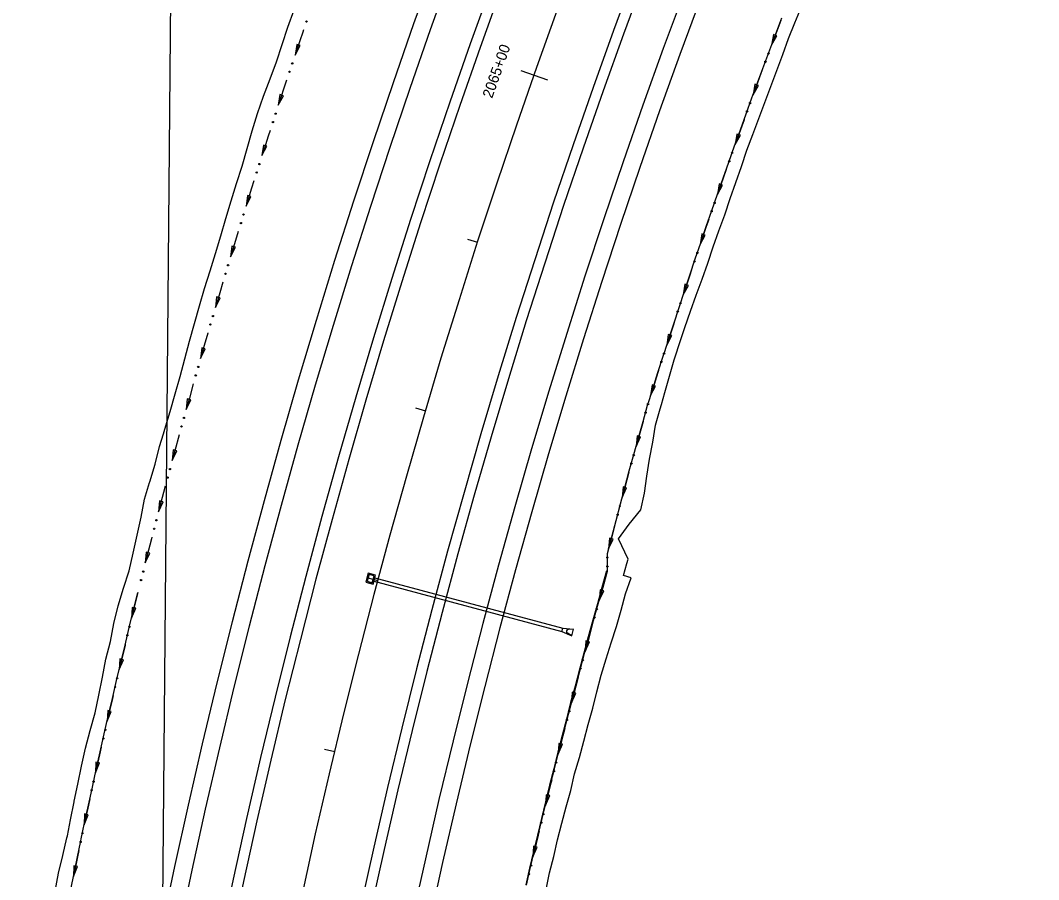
# Model space of a CAD drawing. Extents: x 1611108 to 1749517, y 619561 to 797725.
# Drawn here: x 1713533 to 1714111, y 763041 to 763528 of the extents above; entities that cross this region are included whole.
import ezdxf

# ---------------------------------------------------------------- set-up
doc = ezdxf.new("R2010")
doc.units = 0
for name, color, linetype in [('R_Ditch', 7, 'Continuous'), ('R_Drainage', 7, 'Continuous'), ('R_Horz Alg', 7, 'Continuous'), ('R_Horz Alg Annot', 7, 'Continuous'), ('R_Horz Alg Stationing', 7, 'Continuous'), ('R_Proposed Const Limits', 7, 'Continuous'), ('R_Proposed Road', 7, 'Continuous')]:
    doc.layers.add(name, color=color, linetype=linetype)

msp = doc.modelspace()

# ---------------------------------------------------------------- linework, layer by layer
at = {"layer": 'R_Ditch'}
for p, q in [((1713960.35, 763520.09), (1713959.23, 763514.1)), ((1713959.23, 763514.1), (1713962.33, 763519.35)), ((1713962.33, 763519.35), (1713960.35, 763520.09)), ((1713689.82, 763514.52), (1713688.9, 763508.5)), ((1713689.82, 763514.52), (1713688.9, 763508.5)), ((1713688.9, 763508.5), (1713691.82, 763513.85)), ((1713688.9, 763508.5), (1713691.82, 763513.85)), ((1713691.82, 763513.85), (1713689.82, 763514.52)), ((1713691.82, 763513.85), (1713689.82, 763514.52)), ((1713949.86, 763491.94), (1713948.79, 763485.94)), ((1713948.79, 763485.94), (1713951.85, 763491.21)), ((1713951.85, 763491.21), (1713949.86, 763491.94)), ((1713680.28, 763486.04), (1713679.39, 763480.01)), ((1713680.28, 763486.04), (1713679.39, 763480.01)), ((1713679.39, 763480.01), (1713682.29, 763485.37)), ((1713679.39, 763480.01), (1713682.29, 763485.37)), ((1713682.29, 763485.37), (1713680.28, 763486.04)), ((1713682.29, 763485.37), (1713680.28, 763486.04)), ((1713939.59, 763463.7), (1713938.56, 763457.7)), ((1713938.56, 763457.7), (1713941.58, 763462.99)), ((1713941.58, 763462.99), (1713939.59, 763463.7)), ((1713670.96, 763457.47), (1713670.13, 763451.43)), ((1713670.96, 763457.47), (1713670.13, 763451.43)), ((1713670.13, 763451.43), (1713672.97, 763456.82)), ((1713670.13, 763451.43), (1713672.97, 763456.82)), ((1713672.97, 763456.82), (1713670.96, 763457.47)), ((1713672.97, 763456.82), (1713670.96, 763457.47)), ((1713929.53, 763435.39), (1713928.54, 763429.38)), ((1713928.54, 763429.38), (1713931.52, 763434.69)), ((1713931.52, 763434.69), (1713929.53, 763435.39)), ((1713661.87, 763428.83), (1713661.09, 763422.79)), ((1713661.87, 763428.83), (1713661.09, 763422.79)), ((1713661.09, 763422.79), (1713663.89, 763428.2)), ((1713661.09, 763422.79), (1713663.89, 763428.2)), ((1713663.89, 763428.2), (1713661.87, 763428.83)), ((1713663.89, 763428.2), (1713661.87, 763428.83)), ((1713919.68, 763407.01), (1713918.74, 763400.99)), ((1713918.74, 763400.99), (1713921.68, 763406.32)), ((1713921.68, 763406.32), (1713919.68, 763407.01)), ((1713653, 763400.12), (1713652.27, 763394.08)), ((1713653, 763400.12), (1713652.27, 763394.08)), ((1713652.27, 763394.08), (1713655.03, 763399.51)), ((1713652.27, 763394.08), (1713655.03, 763399.51)), ((1713655.03, 763399.51), (1713653, 763400.12)), ((1713655.03, 763399.51), (1713653, 763400.12)), ((1713910.05, 763378.55), (1713909.15, 763372.52)), ((1713909.15, 763372.52), (1713912.05, 763377.88)), ((1713912.05, 763377.88), (1713910.05, 763378.55)), ((1713644.35, 763371.35), (1713643.66, 763365.3)), ((1713644.35, 763371.35), (1713643.66, 763365.3)), ((1713643.66, 763365.3), (1713646.38, 763370.75)), ((1713643.66, 763365.3), (1713646.38, 763370.75)), ((1713646.38, 763370.75), (1713644.35, 763371.35)), ((1713646.38, 763370.75), (1713644.35, 763371.35)), ((1713900.62, 763350.01), (1713899.78, 763343.98)), ((1713899.78, 763343.98), (1713902.64, 763349.36)), ((1713902.64, 763349.36), (1713900.62, 763350.01)), ((1713635.92, 763342.51), (1713635.28, 763336.45)), ((1713635.92, 763342.51), (1713635.28, 763336.45)), ((1713635.28, 763336.45), (1713637.95, 763341.93)), ((1713635.28, 763336.45), (1713637.95, 763341.93)), ((1713637.95, 763341.93), (1713635.92, 763342.51)), ((1713637.95, 763341.93), (1713635.92, 763342.51)), ((1713891.44, 763321.41), (1713890.64, 763315.37)), ((1713893.46, 763320.77), (1713891.44, 763321.41)), ((1713890.64, 763315.37), (1713893.46, 763320.77)), ((1713627.71, 763313.61), (1713627.11, 763307.55)), ((1713627.71, 763313.61), (1713627.11, 763307.55)), ((1713627.11, 763307.55), (1713629.74, 763313.04)), ((1713627.11, 763307.55), (1713629.74, 763313.04)), ((1713629.74, 763313.04), (1713627.71, 763313.61)), ((1713629.74, 763313.04), (1713627.71, 763313.61)), ((1713882.94, 763292.56), (1713882.36, 763286.5)), ((1713884.98, 763291.99), (1713882.94, 763292.56)), ((1713882.36, 763286.5), (1713884.98, 763291.99)), ((1713619.71, 763284.65), (1713619.17, 763278.58)), ((1713619.71, 763284.65), (1713619.17, 763278.58)), ((1713619.17, 763278.58), (1713621.76, 763284.09)), ((1713619.17, 763278.58), (1713621.76, 763284.09)), ((1713621.76, 763284.09), (1713619.71, 763284.65)), ((1713621.76, 763284.09), (1713619.71, 763284.65)), ((1713874.98, 763263.59), (1713874.45, 763257.52)), ((1713877.03, 763263.04), (1713874.98, 763263.59)), ((1713874.45, 763257.52), (1713877.03, 763263.04)), ((1713611.94, 763255.62), (1713611.44, 763249.55)), ((1713611.94, 763255.62), (1713611.44, 763249.55)), ((1713611.44, 763249.55), (1713613.99, 763255.09)), ((1713611.44, 763249.55), (1713613.99, 763255.09)), ((1713613.99, 763255.09), (1713611.94, 763255.62)), ((1713613.99, 763255.09), (1713611.94, 763255.62)), ((1713867.26, 763234.55), (1713866.77, 763228.48)), ((1713866.77, 763228.48), (1713869.31, 763234.02)), ((1713869.31, 763234.02), (1713867.26, 763234.55)), ((1713604.39, 763226.54), (1713603.94, 763220.46)), ((1713604.39, 763226.54), (1713603.94, 763220.46)), ((1713603.94, 763220.46), (1713606.44, 763226.02)), ((1713603.94, 763220.46), (1713606.44, 763226.02)), ((1713606.44, 763226.02), (1713604.39, 763226.54)), ((1713606.44, 763226.02), (1713604.39, 763226.54)), ((1713861.99, 763205.24), (1713861.39, 763199.18)), ((1713861.39, 763199.18), (1713864.03, 763204.67)), ((1713864.03, 763204.67), (1713861.99, 763205.24)), ((1713596.53, 763195.25), (1713596.13, 763189.17)), ((1713596.13, 763189.17), (1713598.59, 763194.75)), ((1713598.59, 763194.75), (1713596.53, 763195.25)), ((1713853.97, 763176.28), (1713853.42, 763170.22)), ((1713853.42, 763170.22), (1713856.01, 763175.73)), ((1713856.01, 763175.73), (1713853.97, 763176.28)), ((1713589.44, 763166.05), (1713589.09, 763159.97)), ((1713589.09, 763159.97), (1713591.5, 763165.57)), ((1713591.5, 763165.57), (1713589.44, 763166.05)), ((1713846.19, 763147.26), (1713845.68, 763141.19)), ((1713845.68, 763141.19), (1713848.23, 763146.72)), ((1713848.23, 763146.72), (1713846.19, 763147.26)), ((1713582.58, 763136.8), (1713582.26, 763130.72)), ((1713584.64, 763136.33), (1713582.58, 763136.8)), ((1713582.26, 763130.72), (1713584.64, 763136.33)), ((1713838.64, 763118.18), (1713838.18, 763112.1)), ((1713838.18, 763112.1), (1713840.69, 763117.66)), ((1713840.69, 763117.66), (1713838.64, 763118.18)), ((1713575.93, 763107.5), (1713575.66, 763101.42)), ((1713578, 763107.04), (1713575.93, 763107.5)), ((1713575.66, 763101.42), (1713578, 763107.04)), ((1713831.32, 763089.04), (1713830.91, 763082.96)), ((1713830.91, 763082.96), (1713833.38, 763088.53)), ((1713833.38, 763088.53), (1713831.32, 763089.04)), ((1713569.51, 763078.15), (1713569.28, 763072.06)), ((1713569.28, 763072.06), (1713571.58, 763077.71)), ((1713571.58, 763077.71), (1713569.51, 763078.15)), ((1713824.24, 763059.83), (1713823.89, 763053.75)), ((1713823.89, 763053.75), (1713826.3, 763059.35)), ((1713826.3, 763059.35), (1713824.24, 763059.83)), ((1713563.31, 763048.75), (1713563.13, 763042.66)), ((1713563.13, 763042.66), (1713565.38, 763048.32)), ((1713565.38, 763048.32), (1713563.31, 763048.75))]:
    msp.add_line(p, q, dxfattribs=at)
for points in [[(1713820.17, 763037.83), (1713822.36, 763047.26), (1713824.58, 763056.68), (1713826.83, 763066.09), (1713829.1, 763075.5), (1713831.39, 763084.9), (1713833.71, 763094.3), (1713836.05, 763103.68), (1713838.42, 763113.07), (1713840.82, 763122.44), (1713843.23, 763131.81), (1713845.68, 763141.18), (1713848.14, 763150.53), (1713850.63, 763159.88), (1713853.15, 763169.23), (1713855.69, 763178.56), (1713858.25, 763187.89), (1713860.84, 763197.21), (1713863.45, 763206.53), (1713866.09, 763215.84), (1713866.09, 763225.89), (1713868.54, 763235.26), (1713871, 763244.62), (1713873.5, 763253.98), (1713876.01, 763263.33), (1713878.55, 763272.68), (1713881.12, 763282.02), (1713883.71, 763291.36), (1713886.32, 763300.69), (1713888.96, 763310.01), (1713889.75, 763312.51), (1713891.87, 763319.25), (1713894.8, 763328.48), (1713897.75, 763337.7), (1713898.45, 763339.88), (1713900.73, 763346.92), (1713903.74, 763356.13), (1713906.77, 763365.33), (1713909.81, 763374.52), (1713912.89, 763383.71), (1713915.98, 763392.89), (1713919.1, 763402.06), (1713922.24, 763411.22), (1713925.4, 763420.37), (1713928.59, 763429.52), (1713931.79, 763438.66), (1713935.02, 763447.79), (1713938.27, 763456.91), (1713941.55, 763466.02), (1713944.84, 763475.13), (1713948.16, 763484.23), (1713951.5, 763493.32), (1713954.86, 763502.4), (1713958.24, 763511.47), (1713961.65, 763520.54), (1713965.07, 763529.59)], [(1713964.52, 763528.14), (1713961.65, 763520.54), (1713959.23, 763514.1)], [(1713693.73, 763522.7), (1713693.29, 763521.41), (1713689.95, 763511.61), (1713688.9, 763508.5)], [(1713693.73, 763522.7), (1713693.29, 763521.41), (1713689.95, 763511.61), (1713688.9, 763508.5)], [(1713693.74, 763522.74), (1713693.73, 763522.7)], [(1713693.74, 763522.74), (1713693.73, 763522.7)], [(1713953.98, 763500.01), (1713951.5, 763493.32), (1713948.79, 763485.94)], [(1713953.99, 763500.05), (1713953.98, 763500.01)], [(1713684.12, 763494.24), (1713683.37, 763492), (1713680.11, 763482.18), (1713679.4, 763480.01)], [(1713684.12, 763494.24), (1713683.37, 763492), (1713680.11, 763482.18), (1713679.4, 763480.01)], [(1713684.13, 763494.28), (1713684.12, 763494.25)], [(1713684.13, 763494.28), (1713684.12, 763494.25)], [(1713943.64, 763471.81), (1713941.55, 763466.02), (1713938.56, 763457.7)], [(1713943.65, 763471.85), (1713943.64, 763471.81)], [(1713674.73, 763465.71), (1713673.69, 763462.51), (1713670.52, 763452.66), (1713670.13, 763451.43)], [(1713674.73, 763465.71), (1713673.69, 763462.51), (1713670.52, 763452.66), (1713670.13, 763451.43)], [(1713674.74, 763465.75), (1713674.73, 763465.71)], [(1713674.74, 763465.75), (1713674.73, 763465.71)], [(1713933.52, 763443.53), (1713931.79, 763438.66), (1713928.59, 763429.52), (1713928.54, 763429.38)], [(1713933.53, 763443.57), (1713933.52, 763443.53)], [(1713665.58, 763437.1), (1713664.27, 763432.94), (1713661.18, 763423.07), (1713661.09, 763422.79)], [(1713665.58, 763437.1), (1713664.27, 763432.94), (1713661.18, 763423.07), (1713661.09, 763422.79)], [(1713665.59, 763437.14), (1713665.58, 763437.1)], [(1713665.59, 763437.14), (1713665.58, 763437.1)], [(1713923.61, 763415.17), (1713922.24, 763411.22), (1713919.1, 763402.06), (1713918.74, 763400.99)], [(1713923.62, 763415.21), (1713923.61, 763415.17)], [(1713656.65, 763408.42), (1713655.08, 763403.31), (1713652.27, 763394.08)], [(1713656.65, 763408.42), (1713655.08, 763403.31), (1713652.27, 763394.08)], [(1713656.66, 763408.46), (1713656.65, 763408.42)], [(1713656.66, 763408.46), (1713656.65, 763408.42)], [(1713913.91, 763386.74), (1713912.89, 763383.71), (1713909.81, 763374.52), (1713909.15, 763372.52)], [(1713913.92, 763386.78), (1713913.91, 763386.74)], [(1713647.93, 763379.68), (1713646.12, 763373.6), (1713643.66, 763365.3)], [(1713647.93, 763379.68), (1713646.12, 763373.6), (1713643.66, 763365.3)], [(1713647.94, 763379.71), (1713647.93, 763379.68)], [(1713647.94, 763379.71), (1713647.93, 763379.68)], [(1713904.43, 763358.24), (1713903.74, 763356.13), (1713900.73, 763346.92), (1713899.78, 763343.98)], [(1713904.44, 763358.28), (1713904.43, 763358.24)], [(1713639.44, 763350.86), (1713637.39, 763343.82), (1713635.28, 763336.45)], [(1713639.44, 763350.86), (1713637.39, 763343.82), (1713635.28, 763336.45)], [(1713639.45, 763350.9), (1713639.44, 763350.86)], [(1713639.45, 763350.9), (1713639.44, 763350.86)], [(1713895.18, 763329.66), (1713894.8, 763328.48), (1713891.87, 763319.25), (1713890.64, 763315.37)], [(1713895.19, 763329.7), (1713895.18, 763329.66)], [(1713631.16, 763321.99), (1713628.91, 763313.97), (1713627.11, 763307.55)], [(1713631.16, 763321.99), (1713628.91, 763313.97), (1713627.11, 763307.55)], [(1713631.17, 763322.02), (1713631.16, 763321.99)], [(1713631.17, 763322.02), (1713631.16, 763321.99)], [(1713886.39, 763300.94), (1713886.32, 763300.69), (1713883.71, 763291.36), (1713882.36, 763286.5)], [(1713886.4, 763300.98), (1713886.39, 763300.94)], [(1713623.11, 763293.05), (1713620.65, 763284.06), (1713619.17, 763278.58)], [(1713623.11, 763293.05), (1713620.65, 763284.06), (1713619.17, 763278.58)], [(1713623.12, 763293.09), (1713623.11, 763293.05)], [(1713623.12, 763293.09), (1713623.11, 763293.05)], [(1713878.37, 763272), (1713876.01, 763263.33), (1713874.45, 763257.52)], [(1713878.38, 763272.03), (1713878.37, 763272)], [(1713615.27, 763264.05), (1713612.63, 763254.09), (1713611.44, 763249.55)], [(1713615.27, 763264.05), (1713612.63, 763254.09), (1713611.44, 763249.55)], [(1713615.28, 763264.09), (1713615.27, 763264.05)], [(1713615.28, 763264.09), (1713615.27, 763264.05)], [(1713870.57, 763242.99), (1713868.54, 763235.26), (1713866.77, 763228.48)], [(1713870.58, 763243.02), (1713870.57, 763242.99)], [(1713607.66, 763235), (1713607.42, 763234.08), (1713604.85, 763224.06), (1713603.94, 763220.46)], [(1713607.66, 763235), (1713607.42, 763234.08), (1713604.85, 763224.06), (1713603.94, 763220.46)], [(1713607.67, 763235.03), (1713607.66, 763235)], [(1713607.67, 763235.03), (1713607.66, 763235)], [(1713865.69, 763215.95), (1713863.05, 763206.64), (1713860.44, 763197.32), (1713857.85, 763188), (1713855.29, 763178.67), (1713852.75, 763169.33), (1713850.23, 763159.99), (1713847.74, 763150.64), (1713845.27, 763141.28), (1713842.83, 763131.91), (1713840.41, 763122.54), (1713838.02, 763113.17), (1713835.65, 763103.78), (1713833.31, 763094.39), (1713830.99, 763085), (1713828.7, 763075.59), (1713826.43, 763066.19), (1713824.18, 763056.77), (1713821.96, 763047.35), (1713819.76, 763037.92)], [(1713865.46, 763213.61), (1713863.45, 763206.53), (1713861.39, 763199.18)], [(1713865.47, 763213.65), (1713865.46, 763213.61)], [(1713561.08, 763032.57), (1713563.14, 763042.7), (1713565.23, 763052.83), (1713567.35, 763062.94), (1713567.6, 763064.1), (1713569.5, 763073.06), (1713571.67, 763083.17), (1713573.87, 763093.27), (1713576.09, 763103.37), (1713578.34, 763113.46), (1713580.62, 763123.54), (1713582.93, 763133.62), (1713585.26, 763143.69), (1713587.61, 763153.76), (1713590, 763163.82), (1713592.41, 763173.88), (1713594.84, 763183.93), (1713597.31, 763193.97), (1713599.73, 763203.73), (1713599.73, 763203.73)], [(1713599.73, 763203.73), (1713597.31, 763193.97), (1713596.13, 763189.17)], [(1713857.37, 763184.69), (1713855.69, 763178.56), (1713853.42, 763170.22)], [(1713857.38, 763184.72), (1713857.37, 763184.69)], [(1713592.57, 763174.56), (1713592.41, 763173.88), (1713590, 763163.82), (1713589.09, 763159.97)], [(1713592.58, 763174.6), (1713592.57, 763174.56)], [(1713849.52, 763155.69), (1713848.14, 763150.53), (1713845.68, 763141.19)], [(1713849.52, 763155.73), (1713849.52, 763155.69)], [(1713585.64, 763145.33), (1713585.26, 763143.69), (1713582.93, 763133.62), (1713582.26, 763130.72)], [(1713585.65, 763145.37), (1713585.64, 763145.33)], [(1713841.9, 763126.64), (1713840.82, 763122.44), (1713838.42, 763113.07), (1713838.18, 763112.1)], [(1713841.91, 763126.67), (1713841.9, 763126.64)], [(1713578.93, 763116.05), (1713578.34, 763113.46), (1713576.09, 763103.37), (1713575.66, 763101.41)], [(1713578.94, 763116.09), (1713578.93, 763116.05)], [(1713834.52, 763097.52), (1713833.71, 763094.3), (1713831.39, 763084.9), (1713830.92, 763082.96)], [(1713834.53, 763097.56), (1713834.52, 763097.52)], [(1713572.44, 763086.73), (1713571.67, 763083.17), (1713569.5, 763073.06), (1713569.29, 763072.06)], [(1713572.45, 763086.76), (1713572.44, 763086.73)], [(1713827.37, 763068.34), (1713826.83, 763066.09), (1713824.58, 763056.68), (1713823.89, 763053.75)], [(1713827.38, 763068.38), (1713827.37, 763068.34)], [(1713566.18, 763057.35), (1713565.23, 763052.83), (1713563.14, 763042.7), (1713563.13, 763042.66)], [(1713566.19, 763057.38), (1713566.18, 763057.35)]]:
    msp.add_lwpolyline(points, dxfattribs=at)
for centre in [(1713695.4, 763527.44), (1713695.4, 763527.44), (1713957.51, 763509.4), (1713687.34, 763503.75), (1713687.34, 763503.75), (1713955.76, 763504.71), (1713685.74, 763499), (1713685.74, 763499), (1713947.1, 763481.23), (1713677.87, 763475.24), (1713677.87, 763475.24), (1713945.39, 763476.52), (1713676.32, 763470.48), (1713676.32, 763470.48), (1713935.23, 763448.25), (1713936.91, 763452.97), (1713668.64, 763446.65), (1713668.64, 763446.65), (1713667.13, 763441.88), (1713667.13, 763441.88), (1713925.28, 763419.91), (1713926.93, 763424.64), (1713659.64, 763418), (1713659.64, 763418), (1713658.16, 763413.21), (1713658.16, 763413.21), (1713917.16, 763396.24), (1713915.55, 763391.49), (1713649.41, 763384.48), (1713649.41, 763384.48), (1713650.85, 763389.27), (1713650.85, 763389.27), (1713907.61, 763367.76), (1713906.04, 763363), (1713640.88, 763355.68), (1713640.88, 763355.68), (1713642.29, 763360.48), (1713642.29, 763360.48), (1713898.28, 763339.21), (1713896.74, 763334.44), (1713632.57, 763326.81), (1713632.57, 763326.81), (1713633.94, 763331.63), (1713633.94, 763331.63), (1713889.18, 763310.58), (1713887.8, 763305.76), (1713624.48, 763297.88), (1713624.48, 763297.88), (1713625.81, 763302.71), (1713625.81, 763302.71), (1713881.06, 763281.66), (1713879.73, 763276.83), (1713616.6, 763268.9), (1713616.6, 763268.9), (1713617.9, 763273.74), (1713617.9, 763273.74), (1713873.18, 763252.67), (1713871.9, 763247.83), (1713610.21, 763244.7), (1713610.21, 763244.7), (1713608.95, 763239.85), (1713608.95, 763239.85), (1713866.13, 763223.56), (1713866.12, 763218.55), (1713602.75, 763215.6), (1713602.75, 763215.6), (1713601.52, 763210.74), (1713601.52, 763210.74), (1713860.08, 763194.34), (1713858.74, 763189.52), (1713594.97, 763184.3), (1713593.79, 763179.43), (1713852.15, 763165.37), (1713850.84, 763160.54), (1713587.97, 763155.09), (1713586.82, 763150.21), (1713844.45, 763136.34), (1713843.19, 763131.49), (1713581.18, 763125.83), (1713580.07, 763120.94), (1713836.99, 763107.24), (1713835.77, 763102.38), (1713574.62, 763096.52), (1713573.55, 763091.62), (1713828.58, 763073.22), (1713829.77, 763078.09), (1713568.28, 763067.16), (1713567.25, 763062.26), (1713821.64, 763043.99), (1713822.78, 763048.87)]:
    msp.add_circle(centre, 0.375, dxfattribs=at)
at = {"layer": 'R_Drainage'}
for p, q in [((1713733.49, 763212.19), (1713840.74, 763183.58)), ((1713732.98, 763210.26), (1713840.23, 763181.65)), ((1713840.23, 763181.65), (1713840.74, 763183.58)), ((1713840.74, 763183.58), (1713846.92, 763182.97)), ((1713846.92, 763182.97), (1713843.98, 763182.83)), ((1713845.88, 763179.11), (1713846.92, 763182.97)), ((1713840.23, 763181.65), (1713845.88, 763179.11)), ((1713845.88, 763179.11), (1713843.41, 763180.69))]:
    msp.add_line(p, q, dxfattribs=at)
for points in [[(1713729.01, 763209.59), (1713733.19, 763208.47), (1713734.57, 763213.63), (1713730.38, 763214.74)], [(1713729.82, 763210.06), (1713732.72, 763209.29), (1713733.75, 763213.16), (1713730.85, 763213.93)]]:
    msp.add_lwpolyline(points, close=True, dxfattribs=at)
msp.add_arc((1713844.03, 763181.67), 1.17, 92.59517, 237.53533, dxfattribs=at)
at = {"layer": 'R_Horz Alg'}
msp.add_arc((1717426.61, 762226.09), 3819.72, 112.5, 179.5, dxfattribs=at)
at = {"layer": 'R_Horz Alg Annot'}
msp.add_line((1713629.09, 764787.55), (1713607.03, 762259.43), dxfattribs=at)
at = {"layer": 'R_Horz Alg Stationing'}
for points in [[(1713816.99, 763499.7), (1713832.07, 763494.38)], [(1713786.79, 763404.16), (1713792.49, 763402.31)], [(1713757.2, 763308.48), (1713762.95, 763306.78)], [(1713730.12, 763212.05), (1713735.92, 763210.51)], [(1713705.58, 763114.95), (1713711.41, 763113.56)]]:
    msp.add_lwpolyline(points, dxfattribs=at)
at = {"layer": 'R_Proposed Const Limits'}
for points in [[(1713831.38, 763035.31), (1713833.33, 763044.76), (1713835.77, 763054.1), (1713837.85, 763063.52), (1713840.25, 763072.87), (1713842.74, 763082.19), (1713845.36, 763091.48), (1713847.47, 763100.9), (1713850.37, 763110.11), (1713852.71, 763119.47), (1713855.22, 763128.78), (1713857.77, 763138.08), (1713860.05, 763147.46), (1713862.59, 763156.76), (1713865.35, 763166.01), (1713868.21, 763175.22), (1713871.22, 763184.4), (1713873.87, 763193.67), (1713876.39, 763202.97), (1713879.65, 763212.07), (1713875.28, 763213.3), (1713877.17, 763220.13), (1713877.89, 763222.58), (1713872.44, 763234.15), (1713878.38, 763242.51), (1713885.15, 763250.61), (1713887.22, 763260.06), (1713888.44, 763269.76), (1713890, 763279.38), (1713891.85, 763288.91), (1713893.45, 763298.52), (1713896, 763307.85), (1713896.77, 763310.36), (1713898.73, 763317.13), (1713901.29, 763326.45), (1713904, 763335.74), (1713904.74, 763337.89), (1713907.12, 763344.89), (1713910.11, 763354.08), (1713913.23, 763363.24), (1713916.51, 763372.33), (1713919.81, 763381.43), (1713923.03, 763390.54), (1713926.22, 763399.67), (1713929.43, 763408.79), (1713932.66, 763417.9), (1713935.74, 763427.06), (1713938.95, 763436.18), (1713942.24, 763445.26), (1713945.2, 763454.46), (1713948.58, 763463.52), (1713951.99, 763472.57), (1713955.41, 763481.6), (1713958.86, 763490.63), (1713962.27, 763499.67), (1713965.63, 763508.73), (1713968.79, 763517.87), (1713972.56, 763526.78), (1713976.17, 763535.74)], [(1713552.83, 763034.29), (1713554.66, 763044.49), (1713557.09, 763054.57), (1713559.36, 763064.68), (1713559.72, 763065.81), (1713561.41, 763074.83), (1713563.5, 763084.98), (1713563.57, 763085.31), (1713565.69, 763095.11), (1713567.74, 763105.27), (1713570.07, 763115.36), (1713572.64, 763125.4), (1713575.41, 763135.4), (1713577.64, 763145.51), (1713579.66, 763155.68), (1713581.57, 763165.89), (1713584.2, 763175.91), (1713586.14, 763186.1), (1713588.61, 763196.17), (1713591.51, 763206.12), (1713594.78, 763215.98), (1713597.06, 763226.1), (1713599.38, 763236.2), (1713601.54, 763246.35), (1713603.47, 763256.57), (1713606.34, 763266.13), (1713606.45, 763266.5), (1713609.43, 763276.43), (1713611.99, 763286.47), (1713614.25, 763293.76), (1713615.06, 763296.38), (1713617.99, 763306.32), (1713620.83, 763316.29), (1713623.64, 763326.26), (1713626.27, 763336.29), (1713629.09, 763346.27), (1713631.93, 763356.24), (1713634.76, 763366.21), (1713637.6, 763376.18), (1713640.74, 763386.06), (1713643.71, 763395.99), (1713646.7, 763405.92), (1713649.68, 763415.85), (1713652.69, 763425.77), (1713655.64, 763435.71), (1713658.96, 763445.53), (1713661.68, 763455.55), (1713664.61, 763465.5), (1713667.66, 763475.42), (1713671.03, 763485.22), (1713674.75, 763494.92), (1713678.43, 763504.61), (1713681.58, 763514.5), (1713684.87, 763524.33), (1713688.38, 763534.09)]]:
    msp.add_lwpolyline(points, dxfattribs=at)
at = {"layer": 'R_Proposed Road'}
for radius in [3893.72, 3883.72, 3859.72, 3853.72, 3785.72, 3779.72, 3755.72, 3745.72]:
    msp.add_arc((1717426.61, 762226.09), radius, 112.5, 179.5, dxfattribs=at)

# ---------------------------------------------------------------- texts
at = {"layer": 'R_Horz Alg Stationing'}
msp.add_text('2065+00', height=6, rotation=70.56525, dxfattribs=at).set_placement((1713800.69, 763483.56))

doc.saveas('drawing.dxf')
